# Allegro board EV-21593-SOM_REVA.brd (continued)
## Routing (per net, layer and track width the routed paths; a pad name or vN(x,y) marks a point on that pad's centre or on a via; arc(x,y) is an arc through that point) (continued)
DAI0_PIN10: length 48.7
  TOP w0.203: v1(33.82,45.34) U1.Y11
  L4_SIG w0.14: v1(58.04,19.43) 57.53,19.94 57.53,31.62 55.12,34.04 55.12,39.5 53.72,40.89 50.29,40.89 49.05,42.14 38.62,42.14 37.02,43.74 34.82,43.74 33.82,44.74 v1(33.82,45.34)
  BOTTOM w0.14: v1(58.04,19.43) 58.04,19.05 58.17,18.92 59.05,18.92 59.31,19.18 J1.21
DAI0_PIN11: length 51
  TOP w0.203: v1(34.62,45.34) U1.Y12
  L4_SIG w0.14: v1(34.62,45.34) 35.28,44.68 37.16,44.68 38.91,42.93 50.16,42.93 50.55,42.55 53.72,42.55 55.88,40.39 v1(58.55,40.39)
  L5_SIG w0.14: v1(58.55,40.39) 60.58,40.39 61.34,39.62 61.34,20.7 v1(61.85,20.19)
  BOTTOM w0.14: v1(61.85,20.19) 61.34,19.81 J1.23
DAI0_PIN12: length 51.6
  TOP w0.203: v1(34.62,46.14) U1.W12
  L4_SIG w0.14: v1(34.62,46.14) 35.01,45.75 35.59,45.75 35.81,45.52 35.81,45.19 36.07,44.93 37.29,44.93 38.48,43.74 49.91,43.74 50.72,42.93 54.23,42.93 55.88,41.27 58.8,41.27 59.31,40.77 59.31,39.5 58.8,38.99 57.91,38.99 57.4,38.48 57.4,32.89 59.31,30.99 59.31,21.72 58.93,21.34 v1(58.93,20.45)
  BOTTOM w0.14: v1(58.93,20.45) 59.31,20.45 J1.25
DAI0_PIN19: length 48.9
  TOP w0.203: v1(35.42,46.14) U1.W13
  L4_SIG w0.14: v1(59.05,42.93) 59.03,42.95 57.66,42.95 57.43,43.18 50.98,43.18 50.16,43.99 38.61,43.99 37.42,45.18 37.42,46.3 37.18,46.53 35.81,46.53 v1(35.42,46.14)
  L5_SIG w0.14: v1(61.85,25.15) 62.48,25.78 62.48,41.66 61.2,42.94 60.83,42.93 v1(59.05,42.93)
  BOTTOM w0.14: J1.39 61.34,24.89 v1(61.85,25.15)
DAI0_PIN20: length 48.9
  TOP w0.203: v1(34.62,46.94) U1.V12
  L4_SIG w0.14: v1(57.82,43.54) 52.96,43.54 52.85,43.43 51.11,43.43 50.29,44.25 39.16,44.25 38.22,45.18 38.22,47.1 37.98,47.33 35.01,47.33 v1(34.62,46.94)
  L5_SIG w0.14: v1(57.82,43.54) 56.64,43.54 56.26,43.16 56.26,38.1 57.53,36.83 57.53,27.05 v1(58.04,26.54)
  BOTTOM w0.14: v1(58.04,26.54) 58.04,25.78 58.29,25.53 J1.41
DAI1_PIN01: length 52.6
  TOP w0.203: v1(41.02,49.34) U1.R20
  L4_SIG w0.14: v1(41.02,49.34) 44.22,49.34 44.62,49.74 53.21,49.74 54.19,48.77 v1(54.23,48.77)
  L5_SIG w0.14: v1(54.23,48.77) 54.23,47.63 54.62,47.24 54.62,44.96 54.74,44.84 54.74,37.08 56.01,35.81 56.01,14.1 v1(55.12,13.21)
  BOTTOM w0.14: v1(55.12,13.21) 55.63,13.46 J1.4
DAI1_PIN02: length 56.3
  TOP w0.203: v1(39.42,50.14) U1.P18
  L4_SIG w0.14: v1(39.42,50.14) 39.82,50.54 44.29,50.54 45.09,51.34 49.66,51.34 50.32,50.67 53.85,50.67 v1(54.23,50.29)
  L5_SIG w0.14: v1(54.23,50.29) 54.74,49.78 54.74,48.2 55.63,47.31 55.63,45.47 55.12,44.96 55.12,37.34 56.39,36.07 56.39,14.99 56.9,14.48 v1(58.04,14.48)
  BOTTOM w0.14: v1(58.04,14.48) 57.66,14.1 J1.6
DAI1_PIN03: length 54.2
  TOP w0.203: v1(39.42,49.34) U1.R18
  L4_SIG w0.14: v1(39.42,49.34) 39.82,49.74 44.02,49.74 44.82,50.54 49.53,50.54 49.9,50.16 53.59,50.16 v1(54.23,49.53)
  L5_SIG w0.14: v1(55.12,14.48) 55.63,14.99 55.63,35.56 54.36,36.83 54.36,44.44 54.22,44.58 54.22,46.99 53.72,47.49 53.72,49.15 v1(54.23,49.53)
  BOTTOM w0.14: v1(55.12,14.48) 55.63,14.73 J1.8
DAI1_PIN04: length 52.2
  TOP w0.203: v1(41.02,48.54) U1.T20
  L4_SIG w0.14: v1(56.52,47.24) 56.49,47.27 54.25,47.27 52.58,48.94 45.02,48.94 44.22,48.14 42.86,48.14 42.46,48.54 v1(41.02,48.54)
  L5_SIG w0.14: v1(58.04,15.75) 57.28,15.75 56.77,16.26 56.77,36.32 55.5,37.59 55.5,44.7 56.52,45.72 v1(56.52,47.24)
  BOTTOM w0.14: v1(58.04,15.75) 57.66,15.37 J1.10
DAI1_PIN05: length 47.6
  TOP w0.203: v1(41.02,47.74) U1.U20
  L4_SIG w0.14: v1(41.02,47.74) 42.02,47.74 42.42,47.34 44.62,47.34 45.02,47.74 51.42,47.74 v1(52.22,46.94)
  L5_SIG w0.14: v1(55.12,15.75) 52.32,18.54 52.32,24.26 51.69,24.89 51.69,30.61 50.8,31.5 50.8,40.77 51.31,41.27 51.31,43.03 52.22,43.94 v1(52.22,46.94)
  BOTTOM w0.14: J1.12 55.63,16 v1(55.12,15.75)
DAI1_PIN06: length 50
  TOP w0.203: v1(40.22,48.54) U1.T19
  L4_SIG w0.14: v1(56.26,44.7) 56.26,46.1 55.75,46.61 54.36,46.61 54.23,46.74 54.23,46.74 52.83,48.14 44.82,48.14 44.42,47.74 42.62,47.74 42.22,48.14 40.62,48.14 v1(40.22,48.54)
  L5_SIG w0.14: v1(58.04,17.02) 57.4,17.02 57.15,17.27 57.15,36.58 55.88,37.85 55.88,44.32 v1(56.26,44.7)
  BOTTOM w0.14: v1(58.04,17.02) 57.66,16.64 J1.14
DAI1_PIN07: length 47.3
  TOP w0.203: v1(40.22,47.74) U1.U19
  L4_SIG w0.14: v1(53.82,45.74) 53.31,46.25 52.3,46.25 51.21,47.34 45.22,47.34 44.42,46.54 42.46,46.54 41.66,47.34 40.62,47.34 v1(40.22,47.74)
  L5_SIG w0.14: v1(53.82,45.74) 53.42,45.34 53.42,44.3 53.59,44.12 53.59,35.81 53.09,35.31 53.09,26.54 54.23,25.4 54.23,17.91 v1(55.12,17.02)
  BOTTOM w0.14: v1(55.12,17.02) 55.12,17.06 55.17,17.08 55.63,17.27 J1.16
DAI1_PIN08: length 54.4
  TOP w0.203: v1(40.22,49.34) U1.R19
  L4_SIG w0.14: v1(40.22,49.34) 40.62,48.94 44.42,48.94 44.82,49.34 52.84,49.34 54.46,47.72 57.3,47.72 v1(58.67,46.35)
  L5_SIG w0.14: v1(58.67,46.35) 58.67,45.16 59.25,44.58 59.25,44.07 58.62,43.43 58.62,41.91 57.63,40.92 57.63,39.52 58.17,38.99 59.18,38.99 60.45,37.72 60.45,19.69 59.56,18.8 58.55,18.8 v1(58.04,18.29)
  BOTTOM w0.14: J1.18 57.66,17.91 v1(58.04,18.29)
DAI1_PIN09: length 43.7
  TOP w0.203: v1(39.42,48.54) U1.T18
  L4_SIG w0.14: v1(55.12,18.67) 54.48,19.3 53.34,19.3 52.58,20.07 52.58,27.56 51.69,28.45 v1(45.97,28.45)
  L5_SIG w0.14: v1(45.97,28.45) 44.7,29.72 43.31,29.72 42.8,30.23 42.8,35.3 41.02,37.08 41.02,45.94 40.62,46.34 40.62,47.94 40.42,48.14 39.82,48.14 v1(39.42,48.54)
  BOTTOM w0.14: v1(55.12,18.67) 55.63,18.54 J1.20
DAI1_PIN10: length 43.3
  TOP w0.203: v1(39.42,47.74) U1.U18
  L4_SIG w0.14: v1(44.96,28.45) 45.72,29.21 51.56,29.21 52.96,27.81 52.96,20.57 53.59,19.94 54.61,19.94 v1(55.12,19.43)
  L5_SIG w0.14: v1(44.96,28.45) 44.07,29.34 43.18,29.34 42.16,30.35 42.16,31.09 40.62,32.64 40.62,45.54 40.42,45.74 40.02,45.74 39.82,45.94 39.82,47.34 v1(39.42,47.74)
  BOTTOM w0.14: v1(55.12,19.43) 55.63,19.18 J1.22
DAI1_PIN11: length 42.7
  TOP w0.203: v1(40.22,46.94) U1.V19
  L4_SIG w0.14: v1(40.22,46.94) 41.42,45.74 45.02,45.74 45.42,46.14 48.49,46.14 49.42,45.21 52.83,45.21 53.1,44.94 v1(53.82,44.94)
  L5_SIG w0.14: v1(53.82,44.94) 53.82,44.45 53.98,44.3 53.98,35.56 53.47,35.05 53.47,26.92 54.61,25.78 54.61,20.83 v1(55.12,20.32)
  BOTTOM w0.14: v1(55.12,20.32) 55.63,19.81 J1.24
DAI1_PIN12: length 47.8
  TOP w0.203: v1(41.02,46.94) U1.V20
  L4_SIG w0.14: v1(58.67,44.32) 58.17,44.32 57.91,44.07 55.75,44.07 54.48,45.35 53.34,45.35 53.09,45.59 50.61,45.59 49.66,46.54 45.02,46.54 44.62,46.14 41.82,46.14 v1(41.02,46.94)
  L5_SIG w0.14: v1(58.04,20.45) 58.04,24.64 59.82,26.42 59.82,35.43 57.15,38.1 57.15,42.55 57.53,42.93 58,42.93 58.22,43.15 58.22,43.87 v1(58.67,44.32)
  BOTTOM w0.14: v1(58.04,20.45) 57.66,20.45 J1.26
DAI1_PIN19: length 41.4
  TOP w0.203: v1(38.62,46.94) U1.V17
  L4_SIG w0.14: v1(52.62,43.94) 52.06,44.5 39.7,44.5 39.02,45.18 39.02,46.54 v1(38.62,46.94)
  L5_SIG w0.14: v1(52.62,43.94) 52.62,43.18 52.24,42.8 52.24,41.15 51.18,40.09 51.18,31.79 52.24,30.73 52.24,25.49 v1(53.59,24.13)
  BOTTOM w0.14: J1.40 54.99,24.89 54.23,24.13 v1(53.59,24.13)
DAI1_PIN20: length 38.1
  TOP w0.203: v1(39.42,46.14) U1.W18
  L4_SIG w0.14: v1(52.62,44.54) 52.3,44.86 41.61,44.86 40.72,45.75 39.81,45.75 v1(39.42,46.14)
  L5_SIG w0.14: v1(52.62,44.54) 53.21,43.95 53.21,41.4 52.45,40.64 52.45,31.37 52.7,31.12 52.7,26.03 v1(53.59,25.15)
  BOTTOM w0.14: J1.42 54.76,25.53 54.38,25.15 v1(53.59,25.15)
DMC0_A00: length 41
  TOP w0.203: U1.D19 v1(40.22,58.94) ; v1(36.22,74.34) U13.N3
  L5_SIG w0.14: v1(42.62,59.74) 44.22,61.34 44.22,64.61 44.07,64.76 44.07,70.14 44.27,70.34 45.14,70.34 45.34,70.54 45.34,75.74 44.94,76.14 36.82,76.14 36.62,75.94 U13.N3 v1(36.22,74.34)
  BOTTOM w0.14: v1(42.62,59.74) 42.22,59.34 40.62,59.34 v1(40.22,58.94) ; v1(36.22,74.34) 36.22,74.74 37.22,75.74 37.42,75.74 37.62,75.54 37.62,75.34 37.82,75.14 38.02,75.14 38.22,75.34 38.22,75.47 38.42,75.67 38.62,75.67 38.82,75.47 38.82,75.34 39.02,75.14 39.22,75.14 39.42,75.34 39.42,75.54 39.22,75.74 39.22,75.94 39.42,76.14 41.37,76.14 41.42,76.19 RN1.1
DMC0_A01: length 41.3
  TOP w0.203: v1(37.02,78.34) U13.P7 ; U1.D20 v1(41.02,58.94)
  L4_SIG w0.14: v1(37.02,78.34) 37.02,76.34 37.22,76.14 38.62,76.14 38.82,75.94 38.82,75.74 38.62,75.54 38.42,75.54 38.22,75.74 38.02,75.74 37.82,75.54 37.82,75.34 38.22,74.94 38.22,72.54 38.42,72.34 38.42,72.14 38.22,71.94 38.02,71.94 37.82,71.74 37.82,71.54 38.02,71.34 38.02,70.54 37.82,70.34 37.82,70.14 38.22,69.74 38.22,69.34 37.82,68.94 37.82,64.74 38.02,64.54 38.82,64.54 39.02,64.34 39.02,64.14 38.82,63.94 38.02,63.94 37.82,64.14 37.62,64.14 37.42,63.94 37.42,63.74 37.62,63.54 38.82,63.54 39.02,63.34 39.02,60.34 38.82,60.14 38.42,60.14 38.22,59.94 38.22,58.74 38.42,58.54 38.82,58.54 39.02,58.74 39.02,59.14 39.22,59.34 40.62,59.34 v1(41.02,58.94)
  BOTTOM w0.14: v1(37.02,78.34) 37.42,78.74 39.3,78.74 39.5,78.94 39.5,79.34 39.42,79.42 39.42,79.94 39.62,80.14 40.22,80.14 40.42,80.34 40.42,80.54 40.22,80.74 40.22,80.94 40.42,81.14 40.82,81.14 41.02,80.94 41.02,80.74 40.82,80.54 40.82,80.34 41.02,80.14 41.17,80.14 41.42,79.89 RN3.2
DMC0_A02: length 41.1
  TOP w0.14: v1(41.82,59.74) 41.42,59.34 U1.C20
  TOP w0.203: v1(37.02,74.34) U13.P3
  L5_SIG w0.14: v1(37.02,74.34) 37.02,75.54 37.22,75.74 44.43,75.74 44.83,75.34 44.83,71.14 44.63,70.94 43.42,70.94 43.22,70.74 43.22,66.34 43.02,66.14 42.67,66.14 42.55,66.01 42.55,65.66 42.67,65.53 43.56,65.53 43.69,65.4 43.69,64.39 43.82,64.26 43.82,61.94 43.62,61.74 43.42,61.74 43.22,61.94 43.02,61.94 42.82,61.74 42.42,61.74 42.06,62.1 41.75,62.1 41.62,61.98 41.62,60.34 41.82,60.14 v1(41.82,59.74)
  BOTTOM w0.14: v1(37.02,74.34) 37.42,73.94 39.14,73.94 39.42,73.66 39.42,71.94 39.62,71.74 41.22,71.74 41.42,71.94 41.42,73.29 41.62,73.49 RN2.2
DMC0_A03: length 41.3
  TOP w0.203: v1(36.22,73.54) U13.N2 ; U1.C19 v1(40.22,59.74)
  L5_SIG w0.14: v1(36.22,61.34) 36.22,61.94 35.62,62.54 35.22,62.54 35.02,62.74 35.02,64.94 35.22,65.14 36.42,65.14 36.62,65.34 36.62,65.94 37.02,66.34 37.02,66.54 37.22,66.74 37.42,66.74 37.62,66.54 37.82,66.54 38.02,66.74 38.02,66.94 37.82,67.14 37.22,67.14 37.02,67.34 37.02,67.54 37.22,67.74 37.42,67.74 37.62,67.54 37.82,67.54 38.02,67.74 38.02,67.94 37.82,68.14 37.22,68.14 37.02,68.34 37.02,68.54 37.22,68.74 37.42,68.74 37.62,68.54 37.82,68.54 38.02,68.74 38.02,68.94 37.82,69.14 37.22,69.14 37.02,69.34 37.02,70.34 37.22,70.54 37.42,70.54 37.62,70.34 37.82,70.34 38.02,70.54 38.02,70.74 37.82,70.94 37.22,70.94 37.02,71.14 37.02,71.34 37.22,71.54 37.42,71.54 37.62,71.34 37.82,71.34 38.02,71.54 38.02,71.74 37.82,71.94 36.02,71.94 35.82,72.14 35.82,73.14 v1(36.22,73.54)
  BOTTOM w0.14: v1(36.22,61.34) 35.82,60.94 35.82,59.54 36.02,59.34 U1.C19 v1(40.22,59.74) ; v1(36.22,73.54) 36.22,73.84 36.32,73.94 36.54,73.94 36.62,73.86 36.62,72.54 37.32,71.84 37.32,71.74 37.12,71.54 37.02,71.54 36.82,71.34 36.82,71.14 37.02,70.94 37.22,70.94 37.42,71.14 37.62,71.14 38.02,70.74 38.02,70.54 37.82,70.34 36.97,70.34 36.77,70.14 RN5.2
DMC0_A04: length 41.3
  TOP w0.203: U1.A19 v1(40.22,61.34) ; v1(37.02,79.14) U13.P8
  L4_SIG w0.14: v1(40.22,61.34) 40.22,62.34 39.82,62.74 39.82,63.74 39.42,64.14 39.42,64.74 39.22,64.94 38.42,64.94 38.22,65.14 38.22,66.54 38.42,66.74 38.62,66.74 38.82,66.54 38.82,65.94 39.02,65.74 39.22,65.74 39.42,65.94 39.42,66.94 39.22,67.14 38.42,67.14 38.22,67.34 38.22,67.54 38.42,67.74 38.82,67.74 39.02,67.54 39.22,67.54 39.42,67.74 39.42,67.94 39.22,68.14 38.42,68.14 38.22,68.34 38.22,68.54 38.42,68.74 38.82,68.74 39.02,68.54 39.22,68.54 39.42,68.74 39.42,68.94 39.22,69.14 38.82,69.14 38.62,69.34 38.62,69.74 38.82,69.94 39.22,69.94 39.42,70.14 39.42,70.34 39.22,70.54 39.02,70.54 38.82,70.34 38.62,70.34 38.42,70.54 38.42,70.74 38.62,70.94 39.22,70.94 39.42,71.14 39.42,71.34 39.22,71.54 39.02,71.54 38.82,71.74 38.82,72.34 39.02,72.54 39.02,74.94 39.22,75.14 39.22,76.34 39.02,76.54 37.62,76.54 37.42,76.74 U13.P8 v1(37.02,79.14)
  BOTTOM w0.14: v1(37.02,79.14) 37.42,79.54 37.42,80.34 37.82,80.74 37.82,82.14 38.02,82.34 39.17,82.34 39.37,82.54 39.37,84.34 39.17,84.54 37.77,84.54 RN4.1
DMC0_A05: length 41.2
  TOP w0.203: v1(37.02,73.54) U13.P2 ; U1.B20 v1(41.02,60.54)
  L5_SIG w0.14: v1(41.02,60.54) 40.62,60.94 39.22,60.94 39.02,61.14 39.02,61.54 38.82,61.74 37.22,61.74 37.02,61.94 37.02,62.34 36.62,62.74 36.62,63.34 36.82,63.54 36.82,63.74 36.62,63.94 36.62,64.14 36.82,64.34 37.02,64.34 37.42,63.94 37.62,63.94 37.82,64.14 37.82,65.14 38.02,65.34 38.22,65.34 38.42,65.14 38.42,64.94 38.22,64.74 38.22,64.14 38.42,63.94 39.22,63.94 39.42,64.14 39.42,64.34 39.22,64.54 39.02,64.54 38.82,64.74 38.82,64.94 39.02,65.14 39.02,65.54 39.22,65.74 39.82,65.74 40.02,65.94 40.02,66.14 39.82,66.34 39.42,66.34 39.22,66.14 39.02,66.14 38.82,66.34 38.82,66.54 39.02,66.74 39.82,66.74 40.02,66.94 40.02,67.14 39.82,67.34 39.42,67.34 39.22,67.14 39.02,67.14 38.82,67.34 38.82,67.54 39.02,67.74 39.82,67.74 40.02,67.94 40.02,72.54 39.82,72.74 39.82,72.94 40.02,73.14 40.02,73.34 39.82,73.54 39.62,73.54 39.22,73.14 37.42,73.14 v1(37.02,73.54)
  BOTTOM w0.14: RN5.3 37.27,69.79 37.42,69.94 38.22,69.94 38.42,69.74 38.82,69.74 39.02,69.94 39.42,69.94 39.62,70.14 39.62,70.34 39.42,70.54 38.82,70.54 37.82,71.54 37.82,71.94 37.42,72.34 37.42,73.14 v1(37.02,73.54)
DMC0_A06: length 41.3
  TOP w0.203: U1.B18 v1(39.42,60.54) ; v1(37.82,79.14) U13.R8
  L4_SIG w0.14: v1(37.82,79.14) U13.R8 38.22,77.54 38.42,77.34 41.42,77.34 41.62,77.14 41.62,74.14 41.42,73.94 40.22,73.94 40.02,73.74 40.02,73.54 40.22,73.34 40.42,73.34 40.62,73.54 41.42,73.54 41.62,73.34 41.62,73.14 41.42,72.94 40.22,72.94 40.02,72.74 40.02,72.54 40.22,72.34 40.42,72.34 40.62,72.54 41.22,72.54 41.42,72.34 41.42,72.14 41.22,71.94 40.42,71.94 40.22,71.74 40.22,71.54 40.42,71.34 40.62,71.34 40.82,71.54 41.02,71.54 41.22,71.34 41.22,71.14 41.02,70.94 40.42,70.94 40.22,70.74 40.22,62.94 40.62,62.54 40.62,61.14 40.42,60.94 39.82,60.94 v1(39.42,60.54)
  BOTTOM w0.14: RN3.4 41.82,80.89 41.82,81.14 42.02,81.34 42.22,81.34 42.42,81.54 42.42,81.74 42.22,81.94 38.42,81.94 38.22,81.74 38.22,79.54 v1(37.82,79.14)
DMC0_A07: length 41
  TOP w0.203: v1(37.82,73.54) U13.R2 ; U1.A18 v1(39.42,61.34)
  L5_SIG w0.14: v1(37.82,73.54) U13.R2 40.13,73.94 40.42,73.65 40.42,71.14 40.62,70.94 41.82,70.94 42.02,70.74 42.02,70.54 41.82,70.34 41.62,70.34 41.42,70.54 40.62,70.54 40.42,70.34 40.42,70.14 40.62,69.94 41.82,69.94 42.02,69.74 42.02,69.54 41.82,69.34 41.62,69.34 41.42,69.54 40.62,69.54 40.42,69.34 40.42,69.14 40.62,68.94 41.82,68.94 42.02,68.74 42.02,68.54 41.82,68.34 41.62,68.34 41.42,68.54 40.62,68.54 40.42,68.34 40.42,68.14 40.62,67.94 41.82,67.94 42.02,67.74 42.02,67.54 41.82,67.34 41.62,67.34 41.42,67.54 40.62,67.54 40.42,67.34 40.42,65.74 40.22,65.54 40.22,64.54 40.02,64.34 40.02,63.74 39.82,63.54 37.62,63.54 37.42,63.34 37.42,62.34 37.62,62.14 39.22,62.14 39.42,61.94 v1(39.42,61.34)
  BOTTOM w0.14: v1(37.82,73.54) 38.22,73.14 38.22,71.74 39.02,70.94 39.82,70.94 40.02,70.74 40.02,69.16 39.82,68.96 37.77,68.96 RN5.4
DMC0_A08: length 41.3
  TOP w0.203: v1(38.62,79.14) U13.T8 ; U1.A16 v1(37.82,61.34)
  L4_SIG w0.14: v1(41.02,59.74) 41.42,60.14 41.42,61.97 41.02,62.38 41.02,67.94 41.22,68.14 42.02,68.14 42.22,68.34 42.22,68.54 42.02,68.74 41.82,68.74 41.62,68.54 41.22,68.54 41.02,68.74 41.02,68.94 41.22,69.14 42.62,69.14 42.82,69.34 42.82,77.94 42.62,78.14 39.22,78.14 39.02,78.34 U13.T8 v1(38.62,79.14)
  BOTTOM w0.14: v1(37.82,61.34) 38.22,60.94 38.22,60.34 38.42,60.14 40.62,60.14 v1(41.02,59.74) ; v1(38.62,79.14) 39.02,79.54 39.02,80.34 39.22,80.54 39.62,80.54 39.82,80.74 39.82,80.94 39.62,81.14 39.22,81.14 38.98,80.9 38.76,80.9 38.62,81.04 38.62,81.34 38.82,81.54 41.22,81.54 41.42,81.34 41.42,80.59 41.62,80.39 RN3.3
DMC0_A09: length 41.3
  TOP w0.203: v1(37.82,74.34) U13.R3 ; U1.B16 v1(37.82,60.54)
  L5_SIG w0.14: v1(37.82,74.34) 37.82,75.06 37.95,75.18 38.23,75.18 38.35,75.06 38.35,74.99 38.61,74.74 44.13,74.74 44.32,74.55 44.32,74.27 44.2,74.14 43.22,74.14 43.02,74.34 42.62,74.34 42.42,74.14 42.42,73.94 42.62,73.74 44.08,73.74 44.21,73.61 44.21,73.28 44.07,73.14 43.42,73.14 43.22,73.34 43.02,73.34 42.82,73.14 42.82,66.74 42.62,66.54 41.42,66.54 41.22,66.34 41.22,66.14 41.42,65.94 41.42,64.54 40.82,63.94 40.82,62.34 40.62,62.14 v1(39.82,62.14)
  BOTTOM w0.14: v1(39.82,62.14) 39.42,61.74 37.62,61.74 37.42,61.54 37.42,60.94 v1(37.82,60.54) ; RN2.4 41.62,74.49 41.42,74.69 41.42,75.14 41.62,75.34 41.62,75.54 41.42,75.74 41.19,75.74 41,75.54 41,74.72 40.82,74.54 40.62,74.54 40.42,74.74 40.42,75.14 40.62,75.34 40.62,75.54 40.42,75.74 40.22,75.74 40.02,75.54 40.02,74.94 39.82,74.74 U13.R3 v1(37.82,74.34)
DMC0_A10: length 41.2
  TOP w0.203: v1(34.62,78.34) U13.L7 ; U1.A15 v1(37.02,61.34)
  L4_SIG w0.14: v1(37.02,61.34) 37.42,60.94 37.42,57.94 37.22,57.74 36.82,57.74 36.62,57.94 36.62,59.94 36.42,60.14 36.02,60.14 35.82,59.94 35.82,57.94 35.62,57.74 35.22,57.74 35.02,57.94 35.02,61.54 34.62,61.94 34.62,72.94 35.02,73.34 35.02,74.54 34.62,74.94 34.62,77.34 34.82,77.54 34.82,77.74 34.62,77.94 v1(34.62,78.34)
  BOTTOM w0.14: v1(34.62,78.34) 34.62,78.04 34.52,77.94 34.32,77.94 34.22,78.04 34.22,81.14 34.42,81.34 34.84,81.34 35.22,81.72 35.22,82.3 34.84,82.68 34.29,82.68 34.06,82.91 RN7.1
DMC0_A11: length 41.3
  TOP w0.203: U1.B15 v1(37.02,60.54) ; v1(37.82,78.34) U13.R7
  L4_SIG w0.14: v1(39.82,64.74) 39.82,71.54 39.62,71.74 39.62,74.34 39.82,74.54 40.62,74.54 40.82,74.34 41.02,74.34 41.22,74.54 41.22,74.74 41.02,74.94 39.82,74.94 39.62,75.14 39.62,75.34 39.82,75.54 40.62,75.54 40.82,75.34 41.02,75.34 41.22,75.54 41.22,75.74 41.02,75.94 39.82,75.94 39.62,76.14 39.62,76.34 39.82,76.54 40.62,76.54 40.82,76.34 41.02,76.34 41.22,76.54 41.22,76.74 41.02,76.94 38.02,76.94 37.82,77.14 v1(37.82,78.34)
  BOTTOM w0.14: v1(37.82,78.34) 37.42,77.94 36.17,77.94 35.97,77.74 35.97,77.54 36.17,77.34 36.82,77.34 37.05,77.57 41.41,77.57 41.53,77.69 RN1.4 ; v1(37.02,60.54) 36.62,60.94 36.62,61.94 36.82,62.14 39.02,62.14 39.82,62.94 v1(39.82,64.74)
DMC0_A12: length 41.3
  TOP w0.203: U1.B14 v1(36.22,60.54) ; v1(36.22,78.34) U13.N7
  L4_SIG w0.14: v1(36.22,78.34) 35.62,77.74 35.62,77.14 35.42,76.94 35.42,75.54 35.62,75.34 36.42,75.34 36.62,75.14 36.62,72.14 36.42,71.94 35.62,71.94 35.42,71.74 35.42,71.54 35.62,71.34 35.82,71.34 36.02,71.54 36.82,71.54 37.02,71.34 37.02,71.14 36.82,70.94 35.62,70.94 35.42,70.74 35.42,70.54 35.62,70.34 35.82,70.34 36.02,70.54 36.82,70.54 37.02,70.34 37.02,70.14 36.82,69.94 35.62,69.94 35.42,69.74 35.42,69.54 35.62,69.34 35.82,69.34 36.02,69.54 36.82,69.54 37.02,69.34 37.02,69.14 36.82,68.94 35.62,68.94 35.42,68.74 35.42,68.54 35.62,68.34 35.82,68.34 36.02,68.54 36.22,68.54 36.42,68.34 36.42,68.14 36.22,67.94 35.62,67.94 35.42,67.74 35.42,66.14 35.82,65.74 35.82,62.34 36.62,61.54 36.62,60.94 v1(36.22,60.54)
  BOTTOM w0.14: RN4.2 37.27,83.89 37.42,83.74 38.33,83.74 38.53,83.54 38.53,82.94 38.33,82.74 37.42,82.74 37.27,82.59 37.27,80.99 36.62,80.34 36.62,78.74 v1(36.22,78.34)
DMC0_A13: length 41.3
  TOP w0.14: U1.A14 35.82,62.1 36.2,62.48 37.59,62.48 37.82,62.71 v1(37.82,63.14)
  TOP w0.203: v1(38.62,74.34) U13.T3
  L5_SIG w0.14: v1(37.82,63.14) 38.42,62.54 38.82,62.54 39.42,63.14 39.62,63.14 40.02,62.74 40.22,62.74 40.42,62.94 40.42,64.14 41.02,64.74 41.02,65.74 40.82,65.94 40.82,66.74 41.02,66.94 42.22,66.94 42.42,67.14 42.42,71.14 42.22,71.34 41.02,71.34 40.82,71.54 40.82,71.74 41.02,71.94 41.22,71.94 41.42,71.74 42.22,71.74 42.42,71.94 42.42,72.34 42.22,72.54 41.62,72.54 41.42,72.34 41.02,72.34 40.82,72.54 40.82,72.74 41.02,72.94 42.22,72.94 42.42,73.14 42.42,73.34 42.22,73.54 42.02,73.54 41.82,73.34 41.02,73.34 40.82,73.54 40.82,73.74 41.02,73.94 41.22,73.94 41.42,73.74 41.62,73.74 41.82,73.94 41.82,74.14 41.62,74.34 v1(38.62,74.34)
  BOTTOM w0.14: RN2.3 41.22,73.99 41.02,73.79 41.02,73.54 40.82,73.34 40.48,73.34 40.28,73.14 40.28,72.94 40.48,72.74 40.82,72.74 41.02,72.54 41.02,72.34 40.82,72.14 40.02,72.14 39.82,72.34 39.82,73.54 40.22,73.94 40.22,74.14 40.02,74.34 v1(38.62,74.34)
DMC0_A14: length 41.3
  TOP w0.14: v1(40.62,65.34) 40.02,65.94 36.62,65.94 36.07,65.39 36.07,63.13 35.42,62.48 v1(35.42,61.34)
  TOP w0.203: U1.A13 v1(35.42,61.34) ; v1(38.62,78.34) U13.T7
  L4_SIG w0.14: v1(38.62,78.34) 38.62,77.94 38.82,77.74 42.22,77.74 42.42,77.54 42.42,74.74 42.22,74.54 42.22,72.74 42.42,72.54 42.42,71.94 42.22,71.74 41.82,71.74 41.62,71.54 41.62,71.34 41.82,71.14 42.22,71.14 42.42,70.94 42.42,70.74 42.22,70.54 40.82,70.54 40.62,70.34 40.62,70.14 40.82,69.94 41.02,69.94 41.22,70.14 41.91,70.14 42.04,70.01 42.04,69.67 41.91,69.54 40.82,69.54 40.62,69.34 v1(40.62,65.34)
  BOTTOM w0.14: v1(38.62,78.34) 39.82,78.34 40.02,78.54 40.02,79.54 40.22,79.74 40.42,79.74 40.62,79.54 40.62,79.34 40.42,79.14 40.42,78.94 40.62,78.74 40.62,78.54 40.42,78.34 40.42,78.18 40.62,77.98 40.82,77.98 40.98,78.14 41.42,78.14 41.62,78.34 41.62,78.54 41.42,78.74 41.2,78.74 41,78.94 41,79.19 41.2,79.39 RN3.1
DMC0_A15: length 41.3
  TOP w0.203: v1(35.42,78.34) U13.M7 ; U1.B13 v1(35.42,60.54)
  L4_SIG w0.14: v1(35.42,78.34) 35.82,78.74 35.82,81.34 35.42,81.74 34.62,81.74 34.42,81.54 34.42,81.34 34.62,81.14 35.22,81.14 35.42,80.94 35.42,80.74 35.22,80.54 35.02,80.54 34.82,80.74 34.22,80.74 34.02,80.94 33.82,80.94 33.62,80.74 33.62,80.54 33.82,80.34 34.62,80.34 35.02,79.94 35.02,78.14 35.22,77.94 35.22,77.34 35.02,77.14 35.02,75.14 35.22,74.94 35.62,74.94 35.82,74.74 35.82,72.54 35.62,72.34 35.22,72.34 35.02,72.14 35.02,62.34 35.82,61.54 35.82,60.94 v1(35.42,60.54)
  BOTTOM w0.14: RN4.4 36.27,84.54 36.02,84.54 35.88,84.68 35.56,84.68 35.48,84.6 35.48,84.28 35.82,83.94 35.82,82.34 35.62,82.14 35.62,81.34 35.22,80.94 34.82,80.94 34.62,80.74 34.62,78.94 34.82,78.74 35.02,78.74 v1(35.42,78.34)
DMC0_BA0: length 41.2
  TOP w0.203: v1(35.42,73.54) U13.M2 ; U1.B17 v1(38.62,60.54)
  L5_SIG w0.14: v1(38.62,60.54) 38.22,60.94 36.82,60.94 36.62,61.14 36.62,62.14 36.22,62.54 36.22,63.94 36.02,64.14 35.62,64.14 35.42,64.34 35.42,64.54 35.62,64.74 37.22,64.74 37.42,64.94 37.42,65.94 37.62,66.14 38.22,66.14 38.42,66.34 38.42,68.14 38.62,68.34 39.02,68.34 39.22,68.14 39.42,68.14 39.62,68.34 39.62,68.54 39.42,68.74 38.62,68.74 38.42,68.94 38.42,69.14 38.62,69.34 38.82,69.34 39.02,69.14 39.42,69.14 39.62,69.34 39.62,70.14 39.42,70.34 39.22,70.34 39.02,70.14 39.02,69.94 38.82,69.74 38.62,69.74 38.42,69.94 38.42,70.74 38.62,70.94 39.02,70.94 39.22,70.74 39.42,70.74 39.62,70.94 39.62,71.14 39.42,71.34 38.62,71.34 38.42,71.54 38.42,71.74 38.62,71.94 39.02,71.94 39.22,71.74 39.42,71.74 39.62,71.94 39.62,72.34 39.42,72.54 39.22,72.54 39.02,72.34 36.82,72.34 36.62,72.54 36.62,73.74 36.42,73.94 U13.M2 v1(35.42,73.54)
  BOTTOM w0.14: v1(35.42,73.54) 35.42,73.24 35.32,73.14 35.12,73.14 35.02,73.24 35.02,73.74 35.22,73.94 35.62,73.94 35.82,73.74 35.82,72.54 36.02,72.34 36.22,72.34 36.62,71.94 36.62,71.74 36.52,71.64 36.32,71.64 36.22,71.54 36.22,70.94 36.32,70.84 36.52,70.84 36.62,70.74 36.62,70.54 36.22,70.14 36.22,69.89 36.37,69.74 36.37,69.54 36.22,69.39 36.22,69.19 36.27,69.14 RN5.1
DMC0_BA1: length 41.3
  TOP w0.203: U1.A17 v1(38.62,61.34) ; v1(36.22,79.14) U13.N8
  L4_SIG w0.14: v1(36.22,79.14) U13.N8 36.62,77.14 36.42,76.94 36.02,76.94 35.82,76.74 35.82,75.94 36.02,75.74 37.22,75.74 37.42,75.54 37.42,67.74 37.22,67.54 36.02,67.54 35.82,67.34 35.82,67.14 36.02,66.94 36.42,66.94 36.62,67.14 37.22,67.14 37.42,66.94 37.42,66.74 37.22,66.54 36.42,66.54 36.22,66.34 36.22,66.14 36.42,65.94 37.22,65.94 37.42,65.74 37.42,65.34 37.22,65.14 36.42,65.14 36.22,64.94 36.22,64.74 36.42,64.54 36.62,64.54 36.82,64.74 37.02,64.74 37.22,64.54 37.22,64.34 37.02,64.14 36.42,64.14 36.22,63.94 36.22,63.14 36.62,62.74 37.42,62.74 37.62,62.54 37.62,61.94 37.82,61.74 38.02,61.74 38.22,61.94 38.22,62.14 38.02,62.34 38.02,62.54 38.22,62.74 38.42,62.74 38.62,62.54 v1(38.62,61.34)
  BOTTOM w0.14: v1(36.22,79.14) 35.82,79.54 35.22,79.54 35.02,79.74 35.02,80.34 35.22,80.54 35.62,80.54 35.82,80.74 35.82,80.94 36.02,81.14 36.5,81.14 36.7,81.34 36.7,81.54 36.5,81.74 36.34,81.74 36.22,81.86 36.22,82.04 36.32,82.14 36.65,82.14 36.78,82.27 36.78,82.38 36.62,82.54 36.62,82.74 36.82,82.94 37.02,82.94 37.22,83.14 37.22,83.34 36.77,83.79 RN4.3
DMC0_BA2: length 41.3
  TOP w0.14: v1(41.82,58.94) 41.02,58.14 40.22,58.14 U1.E19
  TOP w0.203: v1(35.42,74.34) U13.M3
  L5_SIG w0.14: v1(41.82,58.94) 41.42,59.34 41.42,59.94 41.22,60.14 36.02,60.14 35.82,60.34 35.82,61.74 35.42,62.14 34.82,62.14 34.62,62.34 34.62,65.14 35.02,65.54 35.02,65.74 34.62,66.14 34.62,66.34 34.82,66.54 35.02,66.54 35.22,66.34 35.62,66.34 35.82,66.54 36.02,66.54 36.22,66.34 36.42,66.34 36.62,66.54 36.62,66.74 36.42,66.94 34.82,66.94 34.62,67.14 34.62,67.34 34.82,67.54 35.22,67.54 35.42,67.34 36.33,67.34 36.62,67.63 36.62,71.34 36.42,71.54 35.22,71.54 35.02,71.74 35.02,73.94 v1(35.42,74.34)
  BOTTOM w0.14: RN1.2 41.03,76.69 40.98,76.74 39.72,76.74 39.59,76.61 39.15,76.61 39.02,76.74 38.82,76.74 38.62,76.54 38.62,76.34 38.42,76.14 38.22,76.14 38.02,76.34 38.02,76.54 37.82,76.74 37.62,76.74 35.82,74.94 U13.M3 v1(35.42,74.34)
DMC0_CK: length 33.6
  TOP w0.203: U1.J20 v1(41.02,54.94) ; v1(33.02,78.34) U13.J7
  L4_SIG w0.076: v1(33.02,78.34) 33.02,77.89 32.89,77.76 32.89,74.97 32.62,74.7 32.62,73.19 32.89,72.92 32.89,68.91 32.52,68.54 32.52,67.01 32.89,66.64 32.89,57.27 34.32,55.84 34.75,55.84 35.05,55.54 35.05,54.86 35.31,54.61 35.88,54.61 35.95,54.54 U1.J20 v1(41.02,54.94)
  BOTTOM w0.14: R16.1 33.02,77.42 v1(33.02,78.34)
DMC0_CKE: length 41.3
  TOP w0.203: v1(33.82,79.94) U13.K9 ; U1.H20 v1(41.02,55.74)
  L4_SIG w0.14: v1(41.02,55.74) 41.02,56.04 40.92,56.14 38.42,56.14 38.22,56.34 38.22,56.74 38.02,56.94 34.42,56.94 34.22,57.14 34.22,78.74 34.62,79.14 34.62,79.74 34.42,79.94 v1(33.82,79.94)
  BOTTOM w0.14: v1(33.82,79.94) 33.82,81.54 34.02,81.74 34.62,81.74 34.82,81.94 34.82,82.14 34.62,82.34 34.22,82.34 34.02,82.14 32.89,82.14 32.77,82.27 32.77,82.42 32.89,82.55 33.15,82.55 33.27,82.68 33.27,82.9 33.15,83.02 32.89,83.02 32.77,83.15 32.77,83.44 32.89,83.57 33.44,83.57 33.56,83.69 RN7.2
DMC0_DQ00: length 33.4
  TOP w0.203: v1(25.82,54.94) U1.J2 ; U13.E3 v1(29.82,74.34)
  L5_SIG w0.14: v1(25.82,54.94) 26.22,55.34 26.22,55.94 26.42,56.14 26.82,56.14 27.02,55.94 27.02,55.54 27.22,55.34 27.62,55.34 27.82,55.54 27.82,55.94 28.02,56.14 28.42,56.14 28.62,56.34 28.62,67.14 28.42,67.34 27.62,67.34 27.42,67.54 27.42,67.74 27.62,67.94 28.42,67.94 28.62,68.14 28.62,68.34 28.42,68.54 27.22,68.54 27.02,68.74 27.02,68.94 27.22,69.14 28.42,69.14 28.62,69.34 28.62,69.94 28.22,70.34 28.22,70.54 28.62,70.94 28.62,72.94 28.42,73.14 27.22,73.14 27.02,73.34 27.02,73.74 27.22,73.94 28.42,73.94 28.62,74.14 28.62,74.54 28.82,74.74 29.42,74.74 v1(29.82,74.34)
DMC0_DQ01: length 33.4
  TOP w0.203: v1(25.02,58.14) U1.E1 ; U13.F7 v1(30.62,78.34)
  L5_SIG w0.14: v1(25.02,58.14) 25.42,58.54 25.42,66.14 24.82,66.74 24.82,76.34 25.02,76.54 33.62,76.54 33.82,76.74 33.82,77.74 33.62,77.94 U13.F7 v1(30.62,78.34)
DMC0_DQ02: length 33.4
  TOP w0.203: v1(25.02,55.74) U1.H1 ; U13.F2 v1(30.62,73.54)
  L5_SIG w0.14: v1(25.02,55.74) U1.H1 25.42,54.74 25.62,54.54 29.22,54.54 29.42,54.74 29.42,61.74 29.02,62.14 29.02,68.14 29.22,68.34 29.22,68.54 29.02,68.74 29.02,68.94 29.22,69.14 29.62,69.14 29.82,69.34 29.82,69.54 29.62,69.74 29.22,69.74 29.02,69.94 29.02,70.14 29.22,70.34 30.42,70.34 30.62,70.54 30.62,70.74 30.42,70.94 29.22,70.94 29.02,71.14 29.02,71.34 29.22,71.54 30.42,71.54 30.62,71.74 30.62,71.94 30.42,72.14 29.62,72.14 29.42,72.34 29.42,73.74 29.62,73.94 30.22,73.94 v1(30.62,73.54)
DMC0_DQ03: length 33.5
  TOP w0.203: U13.F8 v1(30.62,79.14) ; v1(25.02,58.94) U1.D1
  L5_SIG w0.14: v1(30.62,79.14) 30.22,78.74 29.62,78.74 29.42,78.54 29.42,78.14 29.22,77.94 28.82,77.94 28.62,78.14 28.62,78.54 28.42,78.74 28.02,78.74 27.82,78.54 27.82,78.14 27.62,77.94 27.22,77.94 27.02,78.14 27.02,78.54 26.82,78.74 26.42,78.74 26.22,78.94 26.02,78.94 25.82,78.74 25.82,78.54 26.02,78.34 26.02,78.14 25.82,77.94 25.02,77.94 24.02,76.94 24.02,66.14 24.62,65.54 24.62,62.34 24.02,61.74 24.02,60.14 24.42,59.74 24.42,59.54 24.02,59.14 24.02,58.14 24.22,57.94 24.42,57.94 24.62,58.14 24.62,58.34 24.42,58.54 24.42,58.74 24.62,58.94 v1(25.02,58.94)
DMC0_DQ04: length 33.4
  TOP w0.203: v1(25.82,56.54) U1.G2 ; U13.H3 v1(32.22,74.34)
  L5_SIG w0.14: v1(32.22,74.34) 31.82,73.94 31.82,67.54 31.02,66.74 31.02,56.14 30.62,55.74 30.62,53.54 30.42,53.34 24.42,53.34 24.22,53.54 24.22,55.94 24.42,56.14 25.42,56.14 v1(25.82,56.54)
DMC0_DQ05: length 33.4
  TOP w0.203: v1(25.82,58.14) U1.E2 ; U13.H8 v1(32.22,79.14)
  L5_SIG w0.14: v1(32.22,79.14) U13.H8 34.02,78.74 34.22,78.54 34.22,77.54 34.42,77.34 34.42,76.34 34.22,76.14 25.42,76.14 25.22,75.94 25.22,67.14 26.22,66.14 26.22,58.54 v1(25.82,58.14)
DMC0_DQ06: length 33.4
  TOP w0.203: v1(25.02,54.94) U1.J1 ; U13.G2 v1(31.42,73.54)
  L5_SIG w0.14: v1(31.42,73.54) 31.02,73.14 31.02,69.14 30.62,68.74 29.82,68.74 29.62,68.54 29.62,68.34 29.82,68.14 30.82,68.14 31.02,67.94 31.02,67.74 30.82,67.54 29.62,67.54 29.42,67.34 29.42,67.14 29.62,66.94 30.22,66.94 30.42,66.74 30.42,66.54 30.22,66.34 29.82,66.34 29.42,65.94 29.42,62.54 29.62,62.34 30.02,62.34 30.22,62.14 30.22,53.94 30.02,53.74 24.82,53.74 24.62,53.94 24.62,54.54 v1(25.02,54.94)
DMC0_DQ07: length 33.4
  TOP w0.203: v1(25.02,56.54) U1.G1 ; U13.H7 v1(32.22,78.34)
  L5_SIG w0.14: v1(32.22,78.34) 31.82,78.74 31.82,79.34 31.62,79.54 25.82,79.54 23.62,77.34 23.62,65.94 24.22,65.34 24.22,62.54 23.62,61.94 23.62,57.94 v1(25.02,56.54)
DMC0_DQ08: length 33.5
  TOP w0.203: U13.D7 v1(29.02,78.34) ; v1(25.82,59.74) U1.C2
  BOTTOM w0.14: v1(25.82,59.74) 26.22,60.14 26.22,66.94 25.82,67.34 23.42,67.34 23.22,67.54 23.22,68.34 23.02,68.54 21.82,68.54 21.62,68.74 21.62,68.94 21.82,69.14 22.62,69.14 22.82,69.34 22.82,69.54 22.62,69.74 21.82,69.74 21.62,69.94 21.62,77.74 21.82,77.94 26.82,77.94 27.02,78.14 27.02,78.54 27.22,78.74 28.62,78.74 v1(29.02,78.34)
DMC0_DQ09: length 33.4
  TOP w0.203: v1(29.02,60.54) U1.B6 ; U13.C3 v1(28.22,74.34)
  BOTTOM w0.14: v1(28.22,74.34) 28.22,74.74 28.42,74.94 28.62,74.94 28.82,75.14 28.82,76.34 29.02,76.54 29.22,76.54 29.42,76.34 29.42,75.14 29.62,74.94 29.82,74.94 30.02,75.14 30.02,76.14 30.22,76.34 30.42,76.34 30.62,76.14 30.62,75.14 30.82,74.94 31.02,74.94 31.22,75.14 31.22,75.94 31.42,76.14 31.62,76.14 31.82,75.94 31.82,66.54 31.22,65.94 31.22,62.34 31.02,62.14 31.02,58.74 30.82,58.54 28.82,58.54 28.62,58.74 28.62,60.14 v1(29.02,60.54)
DMC0_DQ10: length 33.4
  TOP w0.203: U13.C8 v1(28.22,79.14) ; v1(28.22,60.54) U1.B5
  BOTTOM w0.14: v1(28.22,79.14) 28.62,79.54 29.22,79.54 29.42,79.34 29.42,78.14 30.82,76.74 32.02,76.74 32.62,76.14 32.62,69.14 32.22,68.74 32.22,66.34 31.62,65.74 31.62,62.94 31.82,62.74 31.82,57.94 31.62,57.74 28.02,57.74 27.82,57.94 27.82,60.14 v1(28.22,60.54)
DMC0_DQ11: length 33.4
  TOP w0.203: v1(28.22,61.34) U1.A5 ; U13.C2 v1(28.22,73.54)
  BOTTOM w0.14: v1(28.22,73.54) 28.62,73.14 28.62,72.54 28.82,72.34 29.22,72.34 29.42,72.54 29.42,72.94 29.62,73.14 30.02,73.14 30.22,72.94 30.22,71.94 30.02,71.74 28.42,71.74 28.22,71.54 28.22,71.34 28.42,71.14 29.62,71.14 29.82,70.94 29.82,70.74 29.62,70.54 28.42,70.54 28.22,70.34 28.22,70.14 28.42,69.94 29.62,69.94 29.82,69.74 29.82,69.54 29.62,69.34 28.82,69.34 28.62,69.14 28.62,68.94 28.82,68.74 29.62,68.74 29.82,68.54 29.82,68.34 29.62,68.14 28.82,68.14 28.62,67.94 28.62,67.74 28.82,67.54 29.62,67.54 29.82,67.34 29.82,67.14 29.62,66.94 28.82,66.94 28.62,66.74 28.62,66.54 28.82,66.34 29.42,66.34 29.62,66.14 29.62,65.94 29.42,65.74 28.82,65.74 28.62,65.54 28.62,65.34 28.82,65.14 29.42,65.14 29.62,64.94 29.62,64.74 29.42,64.54 28.82,64.54 28.62,64.34 28.62,64.14 28.82,63.94 29.42,63.94 29.62,63.74 29.62,63.54 29.42,63.34 28.82,63.34 28.62,63.14 28.62,62.94 28.82,62.74 29.42,62.74 29.62,62.54 29.62,62.34 29.42,62.14 28.42,62.14 28.22,61.94 v1(28.22,61.34)
DMC0_DQ12: length 33.4
  TOP w0.203: U13.A7 v1(26.62,78.34) ; v1(25.82,61.34) U1.A2
  BOTTOM w0.14: v1(25.82,61.34) 25.82,66.34 25.22,66.94 21.42,66.94 21.22,67.14 21.22,67.34 21.42,67.54 22.62,67.54 22.82,67.74 22.82,67.94 22.62,68.14 21.42,68.14 21.22,68.34 21.22,78.74 21.42,78.94 21.62,78.94 21.82,78.74 21.82,78.54 22.02,78.34 22.22,78.34 22.42,78.54 22.42,78.74 22.62,78.94 22.82,78.94 23.02,78.74 23.02,78.54 23.22,78.34 23.42,78.34 23.62,78.54 23.62,78.74 23.82,78.94 24.02,78.94 24.22,78.74 24.22,78.54 24.42,78.34 24.62,78.34 24.82,78.54 24.82,78.74 25.02,78.94 25.22,78.94 25.42,78.74 25.42,78.54 25.62,78.34 v1(26.62,78.34)
DMC0_DQ13: length 33.4
  TOP w0.203: U13.A2 v1(26.62,73.54) ; v1(26.62,60.54) U1.B3
  BOTTOM w0.14: v1(26.62,60.54) 27.02,60.94 27.02,68.34 26.62,68.74 26.62,69.14 26.42,69.34 24.22,69.34 24.02,69.54 24.02,69.74 24.22,69.94 26.42,69.94 26.62,70.14 26.62,70.34 26.42,70.54 24.22,70.54 24.02,70.74 24.02,70.94 24.22,71.14 26.42,71.14 26.62,71.34 26.62,71.54 26.42,71.74 24.22,71.74 24.02,71.94 24.02,72.14 24.22,72.34 26.02,72.34 26.22,72.54 26.22,72.74 26.02,72.94 24.22,72.94 24.02,73.14 24.02,73.74 24.22,73.94 24.42,73.94 24.82,73.54 25.02,73.54 25.22,73.74 25.62,73.74 25.82,73.54 v1(26.62,73.54)
DMC0_DQ14: length 33.5
  TOP w0.203: v1(26.62,58.94) U1.D3 ; U13.B8 v1(27.42,79.14)
  BOTTOM w0.14: v1(26.62,58.94) 26.22,59.34 25.62,59.34 25.42,59.54 25.42,66.14 25.02,66.54 21.02,66.54 20.82,66.74 20.82,79.34 21.02,79.54 27.02,79.54 v1(27.42,79.14)
DMC0_DQ15: length 33.4
  TOP w0.203: U13.A3 v1(26.62,74.34) ; v1(26.62,61.34) U1.A3
  BOTTOM w0.14: v1(26.62,74.34) 22.22,74.34 22.02,74.14 22.02,73.94 22.42,73.54 22.42,73.34 22.02,72.94 22.02,72.74 22.22,72.54 22.62,72.54 22.82,72.74 23.42,72.74 23.62,72.54 23.62,72.14 23.42,71.94 22.22,71.94 22.02,71.74 22.02,71.54 22.22,71.34 23.42,71.34 23.62,71.14 23.62,70.94 23.42,70.74 22.22,70.74 22.02,70.54 22.02,70.34 22.22,70.14 23.42,70.14 23.62,69.94 23.62,69.14 23.82,68.94 26.02,68.94 26.22,68.74 26.22,68.54 26.02,68.34 23.82,68.34 23.62,68.14 23.62,67.94 23.82,67.74 26.22,67.74 26.62,67.34 v1(26.62,61.34)
DMC0_LDM: length 33.4
  TOP w0.203: v1(25.02,59.74) U1.C1 ; U13.E7 v1(29.82,78.34)
  L5_SIG w0.14: v1(29.82,78.34) 29.82,77.74 30.02,77.54 30.22,77.54 30.42,77.74 30.62,77.74 30.82,77.54 32.02,77.54 32.22,77.34 32.22,77.14 32.02,76.94 29.42,76.94 29.22,77.14 29.22,77.34 29.02,77.54 28.82,77.54 28.62,77.34 28.62,77.14 28.42,76.94 28.22,76.94 28.02,77.14 28.02,77.34 27.82,77.54 27.62,77.54 27.42,77.34 27.42,77.14 27.22,76.94 27.02,76.94 26.82,77.14 26.82,77.74 26.62,77.94 26.42,77.94 26.22,77.74 26.22,77.14 26.02,76.94 24.62,76.94 24.42,76.74 24.42,66.34 25.02,65.74 25.02,62.14 24.42,61.54 24.42,60.34 v1(25.02,59.74)
DMC0_LDQS: length 33.2
  TOP w0.203: U13.F3 v1(30.62,74.34) ; v1(25.82,57.34) U1.F2
  L5_SIG w0.076: v1(25.82,57.34) U1.F2 27.62,56.94 27.82,57.14 27.82,61.72 27.56,61.98 27.56,66.42 26.16,67.82 26.16,69.6 26.29,69.72 27.3,69.72 27.56,69.98 27.56,70.48 27.3,70.74 26.29,70.74 26.16,70.87 26.16,71.12 26.29,71.25 27.56,71.25 27.81,71.5 27.81,72.01 27.56,72.26 26.29,72.26 26.16,72.39 26.16,75.18 26.29,75.31 27.05,75.31 27.18,75.18 28.07,75.18 28.19,75.31 30.73,75.31 30.86,75.18 30.86,74.55 v1(30.62,74.34)
DMC0_ODT: length 41.3
  TOP w0.203: v1(33.82,72.74) U13.K1 ; U1.H19 v1(40.22,55.74)
  L5_SIG w0.14: v1(33.82,72.74) 33.42,72.34 33.42,66.74 33.02,66.34 33.02,58.54 33.22,58.34 33.42,58.34 33.62,58.54 34.82,58.54 35.02,58.34 35.02,57.94 35.22,57.74 35.62,57.74 35.82,57.94 35.82,58.34 36.02,58.54 36.42,58.54 36.62,58.34 36.62,57.94 36.82,57.74 37.22,57.74 37.42,57.94 37.42,58.34 37.62,58.54 39.62,58.54 40.62,57.54 40.62,57.14 40.42,56.94 40.02,56.94 39.82,56.74 39.82,55.54 40.02,55.34 41.42,55.34 41.62,55.54 41.62,55.94 41.42,56.14 40.62,56.14 v1(40.22,55.74)
  BOTTOM w0.14: RN6.2 33.57,69.44 33.42,69.59 33.42,69.94 33.62,70.14 33.82,70.14 34.02,69.94 34.42,69.94 34.62,70.14 34.62,70.34 34.42,70.54 33.62,70.54 33.42,70.74 33.42,70.94 33.62,71.14 33.82,71.14 34.02,70.94 34.42,70.94 34.62,71.14 34.62,71.34 34.42,71.54 33.82,71.54 33.42,71.94 33.42,72.34 v1(33.82,72.74)
DMC0_RZQ: length 4.7
  TOP w0.203: v1(40.22,56.54) U1.G19
  BOTTOM w0.14: R1.1 42.82,54.94 41.62,56.14 40.62,56.14 v1(40.22,56.54)
DMC0_UDM: length 33.4
  TOP w0.203: v1(29.02,61.34) U1.A6 ; U13.D3 v1(29.02,74.34)
  BOTTOM w0.14: v1(29.02,74.34) 29.42,73.94 30.82,73.94 31.02,73.74 31.02,72.54 30.62,72.14 30.62,71.94 30.82,71.74 30.92,71.74 31.12,71.94 31.22,71.94 31.42,71.74 31.42,71.14 31.22,70.94 30.82,70.94 30.62,71.14 30.42,71.14 30.22,70.94 30.22,70.74 30.42,70.54 31.22,70.54 31.42,70.34 31.42,70.14 31.22,69.94 30.42,69.94 30.22,69.74 30.22,69.34 30.42,69.14 31.22,69.14 31.42,68.94 31.42,68.74 31.22,68.54 30.42,68.54 30.22,68.34 30.22,68.14 30.42,67.94 31.22,67.94 31.42,67.74 31.42,67.54 31.22,67.34 30.42,67.34 30.22,67.14 30.22,66.94 30.42,66.74 30.82,66.74 31.02,66.54 31.02,66.34 30.82,66.14 30.22,66.14 30.02,65.94 30.02,65.74 30.22,65.54 30.62,65.54 30.82,65.34 30.82,65.14 30.62,64.94 30.22,64.94 30.02,64.74 30.02,64.54 30.22,64.34 30.62,64.34 30.82,64.14 30.82,63.94 30.62,63.74 30.22,63.74 30.02,63.54 30.02,63.34 30.22,63.14 30.62,63.14 30.82,62.94 30.82,62.74 30.62,62.54 30.22,62.54 30.02,62.34 30.02,61.94 30.22,61.74 30.22,59.54 30.02,59.34 29.62,59.34 29.42,59.54 U1.A6 v1(29.02,61.34)
DMC0_UDQS: length 33.4
  TOP w0.203: v1(27.42,60.54) U1.B4 ; U13.C7 v1(28.22,78.34)
  BOTTOM w0.089: v1(28.22,78.34) 28.55,77.93 28.55,77.37 27.57,76.39 25.34,76.39 24.64,77.09 22.54,77.09 22.4,76.95 22.4,75.55 22.54,75.41 22.96,75.41 23.1,75.55 23.1,76.25 23.38,76.53 23.94,76.53 24.22,76.25 24.22,75.55 24.36,75.41 25.9,75.41 26.31,75.83 27.29,75.83 27.57,75.55 27.57,75.1 27.82,74.85 27.82,72.34 27.57,72.09 27.57,69.27 27.99,68.85 27.99,62.42 27.82,62.25 27.82,60.94 v1(27.42,60.54)
DMC0_VREF: length 48.1
  TOP w0.305: R7.2 44.7,80.94 44.7,80.14 44.94,77.98 44.96,77.85 44.83,77.98 ; R8.2 46.98,75.78 45.09,77.72 45.06,75.78 45.06,75.31 45.05,75.19 44.95,66.79 44.95,66.68 44.83,66.79
  TOP w0.406: v2(44.83,65.53) 44.83,74.3 45.05,75.19 45.09,75.31 45.06,75.78 44.96,77.85
  L4_SIG w0.305: v2(44.83,65.53) 44.58,65.53 44.58,56.54 v1(45.42,56.54)
  BOTTOM w0.406: R2.1 v1(45.42,56.54) C10.1 47.02,56.54
HADC0_VIN0: length 48
  TOP w0.203: v1(40.22,50.94) U1.N19
  L4_SIG w0.14: v1(40.22,50.94) 40.62,51.34 44.07,51.34 45.43,52.7 55.24,52.7 60.58,47.37 60.58,28.45 60.83,28.19 62.23,28.19 62.48,27.94 62.48,27.3 62.23,27.05 v1(61.85,27.05)
  BOTTOM w0.14: v1(61.85,27.05) 61.47,27.43 J1.47
HADC0_VIN1: length 45.1
  TOP w0.203: v1(41.02,50.94) U1.N20
  L4_SIG w0.14: v1(41.02,50.94) 44.2,50.94 45.58,52.32 54.99,52.32 60.2,47.12 60.2,27.94 60.45,27.69 v1(61.85,27.69)
  BOTTOM w0.14: J1.49 61.47,28.07 v1(61.85,27.69)
HADC0_VIN2: length 46.8
  TOP w0.203: v1(40.22,51.74) U1.M19
  L4_SIG w0.14: v1(40.22,51.74) 40.62,52.14 43.81,52.14 45.14,53.47 55.75,53.47 61.34,47.88 61.34,30.1 61.59,29.84 62.23,29.84 62.48,29.59 62.48,28.96 62.23,28.7 v1(61.85,28.7)
  BOTTOM w0.14: J1.51 61.85,28.7 v1(61.85,28.7)
HADC0_VIN3: length 43.9
  TOP w0.203: v1(41.02,51.74) U1.M20
  L4_SIG w0.14: v1(61.85,29.34) 61.21,29.34 60.96,29.59 60.96,47.62 55.5,53.09 45.29,53.09 43.94,51.74 v1(41.02,51.74)
  BOTTOM w0.14: J1.53 61.85,29.34 v1(61.85,29.34)
ID0: length 18.1
  TOP w0.14: v2(52.45,10.54) R126.2 53.21,10.51 53.21,9.84 52.58,9.2 U22.1
  L4_SIG w0.14: v2(52.45,10.54) 50.04,10.54 48.39,8.89 40.13,8.89 v1(39.5,8.26)
  BOTTOM w0.14: J2.76 39.42,7.66 39.5,7.74 v1(39.5,8.26)
ID1: length 16.8
  TOP w0.14: U22.3 52.45,7.28 v2(52.45,5.97) R125.2
  L4_SIG w0.14: v2(52.45,5.97) 49.91,5.97 47.62,8.26 v1(40.51,8.26)
  BOTTOM w0.14: v1(40.51,8.26) 40.05,7.79 J2.78
INTVCC: length 16.5
  TOP w0.254: R56.1 20.7,14.1 19.81,14.99 U15.3
  TOP w0.305: R56.1 22.86,13.82 22.73,13.69 C167.2 22.73,13.33 v2(24.13,13.33) ; R58.1 v2(15.24,12.19)
  L4_SIG w0.305: v2(24.13,13.33) 23.62,12.83 18.8,12.83 18.41,13.21 16.26,13.21 v2(15.24,12.19)
JTG0_TCK/SWCLK: length 94.9
  TOP w0.14: v1(33.82,62.34) 33.02,63.14 33.02,66.93 31.88,68.07 26.03,68.07 25.15,68.96 25.15,71.63 24.64,72.14 v2(9.02,72.14) ; v1(5.46,28.7) 4.06,30.1 4.06,46.35 2.79,47.62 2.79,54.74 3.18,55.12 5.71,55.12 5.97,54.86 5.97,53.59 P1.4
  TOP w0.203: U1.B11 v1(33.82,59.74)
  L4_SIG w0.14: v2(8.89,52.96) 5.97,52.96 P1.4
  L5_SIG w0.14: v2(9.02,72.14) 9.02,71.5 7.49,69.98 7.49,60.58 9.4,58.67 9.4,53.47 v2(8.89,52.96)
  BOTTOM w0.14: v1(5.46,28.7) J3.50 ; v1(33.82,59.74) v1(33.82,62.34)
JTG0_TDI: length 116.3
  TOP w0.14: v1(8.51,27.18) 8.26,27.43 4.06,27.43 2.54,28.96 2.54,45.47 1.27,46.74 1.27,56.13 2.29,57.15 5.71,57.15 6.99,55.88 6.99,53.85 7.62,53.21 7.62,50.8 6.99,50.16 P1.8
  TOP w0.203: v1(35.42,59.74) U1.C13
  BOTTOM w0.14: v1(35.42,59.74) U1.C13 35.02,58.74 35.22,58.54 35.62,58.54 35.82,58.34 35.82,57.14 36.02,56.94 36.42,56.94 36.62,56.74 36.62,52.34 36.42,52.14 32.82,52.14 32.62,51.94 32.62,47.54 32.42,47.34 28.02,47.34 27.82,47.14 27.82,44.32 27.57,44.07 25.4,44.07 25.15,43.81 25.15,37.34 24.77,36.96 20.95,36.96 20.57,36.58 20.57,25.15 19.94,24.51 10.16,24.51 9.27,25.4 9.27,26.42 v1(8.51,27.18) 8,27.43 J3.54
JTG0_TDO/SWO: length 102.1
  TOP w0.14: 5.08,51.43 6.73,51.43 7.11,51.82 7.11,52.96 6.48,53.59 6.48,55.63 5.46,56.64 2.67,56.64 1.78,55.75 1.78,47.12 3.05,45.85 3.05,29.34 4.57,27.81 8.26,27.81 v1(8.51,28.07)
  TOP w0.203: v1(33.82,58.94) U1.C11
  BOTTOM w0.14: J3.52 8.51,28.07 v1(8.51,28.07) 9.4,28.96 18.54,28.96 19.18,29.59 19.18,38.73 20.95,40.51 24.51,40.51 24.77,40.77 24.77,44.2 25.02,44.45 26.77,44.45 27.02,44.7 27.02,47.94 27.22,48.14 31.62,48.14 31.82,48.34 31.82,55.14 32.02,55.34 34.02,55.34 35.02,56.34 35.02,58.34 34.82,58.54 34.22,58.54 v1(33.82,58.94)
JTG0_TMS/SWDIO: length 93.8
  TOP w0.14: v1(8.51,29.34) 7.37,28.19 4.95,28.19 3.56,29.59 3.56,46.1 2.29,47.37 2.29,55.24 2.92,55.88 v2(5.08,55.88)
  TOP w0.203: U1.C12 v1(34.62,59.74)
  L5_SIG w0.14: v2(5.08,55.88) P1.2
  BOTTOM w0.14: J3.48 8.51,29.34 v1(8.51,29.34) 18.29,29.34 18.8,29.84 18.8,38.99 20.32,40.51 20.32,44.45 20.7,44.83 26.03,44.83 26.22,45.02 26.22,56.74 26.42,56.94 32.42,56.94 32.62,57.14 32.62,59.14 32.82,59.34 U1.C12 v1(34.62,59.74)
N1: length 149.1
  TOP w0.14: v1(32.19,5.33) 31.69,5.84 24.38,5.84 22.35,7.87 v1(22.35,9.14)
  TOP w0.203: v1(30.62,59.74) U1.C8
  L4_SIG w0.14: v1(30.62,59.74) 30.22,59.34 22.22,59.34 v1(21.82,58.94) ; v1(22.35,9.14) 22.35,7.75 21.97,7.37 19.69,7.37 19.05,6.73 19.05,5.71 v1(18.67,5.33)
  L5_SIG w0.14: v1(21.82,58.94) 21.82,54.84 21.34,54.36 21.34,44.96 20.32,43.94 19.91,43.94 19.02,43.05 19.02,40.55 19.43,40.14 19.43,30.35 21.34,28.45 21.34,16 22.35,14.99 v1(22.35,9.14)
  BOTTOM w0.14: v1(32.19,5.33) 31.8,5.71 J2.52 31.8,8.38 32.05,8.64 38.23,8.64 38.61,9.02 52.7,9.02 53.98,10.29 53.98,16.51 52.7,17.78 52.7,21.08 51.69,22.1 51.69,32.89 53.85,35.05 53.85,40.26 54.99,41.4 J1.92 ; J2.30 24.81,8.51 24.26,9.06 24.26,9.4 24,9.65 22.86,9.65 v1(22.35,9.14) ; v1(18.67,5.33) 19.1,5.71 J2.12
N2: length 149.1
  TOP w0.203: v1(29.82,60.54) U1.B7
  L4_SIG w0.14: v1(29.82,60.54) 29.42,60.94 24.42,60.94 24.02,60.54 v1(23.02,60.54) ; v1(58.8,35.43) 59.82,34.42 59.82,24.77 60.32,24.26 61.98,24.26 62.36,23.88 62.36,11.18 61.72,10.54 56.26,10.54 55.5,9.78 53.59,9.78 53.09,9.27 53.09,4.83 52.2,3.94 46.99,3.94 v1(46.48,4.45) 46.86,4.83 46.86,5.46 45.34,6.99 38.61,6.99 36.96,8.64 33.66,8.64 32.64,7.62 30.86,7.62 28.57,9.91 24.26,9.91 v1(23.49,9.14)
  L5_SIG w0.14: v1(23.02,60.54) 22.22,59.74 22.22,54.61 21.72,54.11 21.72,44.96 20.62,43.86 20.62,42.94 19.42,41.74 19.42,40.74 19.82,40.34 19.82,30.73 21.84,28.7 21.84,16.38 22.86,15.37 22.86,9.78 v1(23.49,9.14)
  BOTTOM w0.14: v1(46.48,4.45) 46.4,4.06 J2.97 ; J2.28 24.18,8.46 v1(23.49,9.14) ; v1(58.8,35.43) 58.8,36.07 57.91,36.96 57.91,40.51 57.66,40.77 J1.90
N3: length 135.1
  TOP w0.14: v1(23.11,4.45) 23.56,4.89 30.86,4.89 v1(31.31,5.33)
  TOP w0.203: v1(29.82,59.74) U1.C7
  L4_SIG w0.14: v1(29.82,59.74) 29.42,60.14 21.82,60.14 v1(20.62,58.94) ; v1(30.99,8.13) 31.75,8.89 37.85,8.89 39.12,10.16 45.59,10.16 53.59,18.16 v1(53.59,18.67)
  L5_SIG w0.14: v1(20.62,58.94) 19.32,57.64 19.32,56.44 18.22,55.34 18.22,40.19 18.67,39.74 18.67,30.23 16.89,28.45 16.89,22.48 20.32,19.05 20.32,15.24 21.34,14.22 21.34,11.68 20.83,11.18 20.83,7.49 22.61,5.71 22.61,4.95 v1(23.11,4.45)
  BOTTOM w0.14: J2.23 22.91,4.06 v1(23.11,4.45) ; v1(31.31,5.33) 31.16,5.71 J2.50 31.16,7.75 v1(30.99,8.13) ; J1.88 54.99,40.13 54.36,39.5 54.36,34.29 52.58,32.51 52.58,24 54.36,22.23 54.36,19.43 v1(53.59,18.67)
N4: length 165.9
  TOP w0.14: v2(43.05,88.9) R115.2 ; v1(51.82,41.78) 49.26,44.34 v1(21.82,44.34)
  TOP w0.203: U1.C9 v1(31.42,59.74)
  L4_SIG w0.14: v1(18.41,58.93) 19.69,57.66 21.74,57.66 v1(23.02,58.94) 24.02,58.94 24.42,58.54 30.22,58.54 v1(31.42,59.74)
  L5_SIG w0.14: v1(25.78,8.13) 24.89,8.13 24.26,8.76 24.26,11.18 23.49,11.94 23.49,15.62 22.35,16.76 22.35,28.96 20.22,31.09 20.22,41.74 21.82,43.34 v1(21.82,44.34) 22.1,44.62 22.1,53.83 22.62,54.36 22.62,58.54 v1(23.02,58.94) ; v1(18.41,58.93) 18.41,65.91 20.57,68.07 20.57,72.26 21.84,73.53 21.84,86.49 22.61,87.25 28.45,87.25 29.84,88.65 40.26,88.65 41.15,89.54 42.42,89.54 v2(43.05,88.9)
  BOTTOM w0.14: J1.98 55.24,43.31 53.21,41.27 52.32,41.27 v1(51.82,41.78) ; v1(25.78,8.13) 26.86,8.13 27.35,7.64 J2.38 J2.37
N5: length 173.1
  TOP w0.14: v1(19.82,44.54) 20.22,44.94 20.22,45.54 20.62,45.94 23.22,45.94 24.42,44.74 49.75,44.74 v1(52.7,41.78) ; v2(50.16,88.9) R114.2
  TOP w0.203: v1(29.82,61.34) U1.A7
  L4_SIG w0.14: v1(29.82,61.34) 29.42,61.74 21.82,61.74 v1(20.62,60.54)
  L5_SIG w0.14: v2(50.16,88.9) 49.53,88.27 30.1,88.27 28.7,86.87 22.99,86.87 22.35,86.23 22.35,73.15 21.21,72.01 21.21,61.13 v1(20.62,60.54) 21.08,60.08 21.08,57.66 20.76,57.34 20.34,57.34 19.94,56.94 19.94,54.26 19.11,53.43 19.11,52.52 19.3,52.32 19.3,51.34 18.89,50.93 18.89,45.47 v1(19.82,44.54) 19.82,44.51 18.62,43.31 18.62,40.37 19.05,39.94 19.05,30.1 20.83,28.32 20.83,15.62 21.84,14.6 21.84,8.76 24,6.6 24.89,6.6 25.65,5.84 25.65,5.08 v1(26.29,4.45)
  BOTTOM w0.14: J1.100 55.37,43.94 53.21,41.78 v1(52.7,41.78) ; J2.35 26.72,4.06 v1(26.29,4.45) 26.72,4.87 J2.36
N6: length 60.9
  TOP w0.14: R70.1 v1(33.82,40.14)
  TOP w0.203: v1(29.82,46.14) U1.W7
  L4_SIG w0.14: v1(29.82,46.14) 30.22,45.74 30.22,42.34 32.42,40.14 v1(33.82,40.14) ; v1(26.16,5.33) 27.3,6.48 37.21,6.48 v1(38.35,5.33)
  L5_SIG w0.14: v1(38.35,5.33) 38.35,6.86 37.85,7.37 37.85,25.78 34.29,29.34 34.29,39.67 v1(33.82,40.14)
  BOTTOM w0.14: v1(26.16,5.33) 26.08,5.71 J2.34
N7: length 58.8
  TOP w0.203: v1(29.02,45.34) U1.Y6
  L4_SIG w0.14: v1(35.31,8.13) 34.54,7.37 30.73,7.37 28.45,9.65 24.64,9.65 v1(23.49,8.51)
  L5_SIG w0.14: v1(35.31,8.13) 35.31,10.79 35.94,11.43 35.94,12.45 34.29,14.1 34.29,17.02 35.05,17.78 35.05,18.8 34.42,19.43 34.42,20.57 35.05,21.21 35.05,25.02 31.62,28.45 31.62,32.35 30.48,33.5 30.48,37.93 29.42,38.99 29.42,43.94 29.02,44.34 v1(29.02,45.34)
  BOTTOM w0.14: J2.20 21.64,7.67 22.48,8.51 v1(23.49,8.51)
N8: length 72.3
  TOP w0.14: v1(38.35,4.45) 37.72,3.81 31.24,3.81 30.23,2.79 27.43,2.79 v1(26.29,1.65)
  TOP w0.203: v1(30.62,46.94) U1.V8
  L4_SIG w0.14: v1(26.29,1.65) 25.53,2.41 21.97,2.41 20.83,3.56 20.83,4.83 v1(20.32,5.33)
  L5_SIG w0.14: v1(30.62,46.94) U1.V8 32.42,47.34 33.27,46.49 33.27,37.1 33.93,36.45 33.93,28.81 36.83,25.91 36.83,18.44 36.7,18.31 36.7,13.72 37.21,13.21 37.21,7.11 37.85,6.48 37.85,4.95 v1(38.35,4.45)
  BOTTOM w0.14: v1(20.32,5.33) 20.37,5.71 J2.16 ; J2.33 26.08,2.16 v1(26.29,1.65)
N9: length 132.3
  TOP w0.14: v2(13.84,76.58) 13.46,76.44 U11.5 ; v1(18.16,8.13) 18.16,7.11 17.15,6.1 17.15,4.45 18.29,3.3 20.83,3.3 v1(22.48,1.65) 22.99,1.14 30.61,1.14 v1(31.12,1.65)
  TOP w0.203: v1(25.82,46.94) U1.V2
  L4_SIG w0.14: v1(9.02,43.69) 9.53,44.2 16.64,44.2 17.02,43.81 19.94,43.81 20.95,44.83 23.55,44.83 23.96,45.24 23.96,45.85 24.66,46.54 25.42,46.54 v1(25.82,46.94)
  L5_SIG w0.14: v1(18.16,8.13) 17.27,7.24 11.68,7.24 7.37,11.56 7.37,25.27 7.11,25.53 7.11,41.02 9.02,42.93 v1(9.02,43.69) 6.99,45.72 6.99,47.37 7.62,48.01 7.62,55.5 5.84,57.28 5.84,72.64 6.6,73.41 12.45,73.41 12.95,73.91 12.95,75.69 v2(13.84,76.58)
  BOTTOM w0.14: J2.49 31.16,2.16 v1(31.12,1.65) ; J2.10 18.46,7.62 v1(18.16,8.13) ; J2.21 22.27,2.16 v1(22.48,1.65)
N10: length 132.6
  TOP w0.14: v2(11.05,78.74) 11.43,78.39 U11.2 ; v1(17.65,5.33) 17.65,4.7 18.41,3.94 20.83,3.94 v1(21.34,4.45) 22.23,3.56 29.34,3.56 v1(30.23,4.45)
  TOP w0.203: v1(26.62,47.74) U1.U3
  L4_SIG w0.14: v2(5.21,46.48) 6.6,46.48 7.24,47.12 8.51,47.12 9.91,45.72 14.99,45.72 15.37,46.1 23.11,46.1 24.35,47.34 26.22,47.34 v1(26.62,47.74)
  L5_SIG w0.14: v1(17.65,5.33) 16.13,6.86 11.43,6.86 6.99,11.3 6.99,24.89 6.6,25.27 6.6,41.02 4.32,43.31 4.32,45.59 v2(5.21,46.48) 7.11,48.39 7.11,55.24 5.33,57.02 5.33,77.6 6.48,78.74 v2(11.05,78.74)
  BOTTOM w0.14: v1(17.65,5.33) 17.83,5.71 J2.8 ; J2.19 21.64,4.06 v1(21.34,4.45) ; v1(30.23,4.45) 30.53,4.06 J2.47
N11: length 131.8
  TOP w0.14: v2(14.73,76.58) 15.89,77.74 U11.12 ; v1(17.4,8.13) 17.4,7.43 16.89,6.92 16.89,4 18.03,2.86 19.69,2.86 v1(20.95,1.65)
  TOP w0.203: v1(25.02,46.94) U1.V1
  L4_SIG w0.14: v1(20.95,1.65) 21.46,1.14 29.08,1.14 v1(29.59,1.65) ; v2(8.13,46.48) 9.27,45.34 15.49,45.34 16,45.85 23.37,45.85 24.46,46.94 v1(25.02,46.94)
  L5_SIG w0.14: v2(14.73,76.58) 13.59,75.44 13.59,73.53 12.95,72.9 8.38,72.9 7.49,72.01 7.49,71.12 6.86,70.48 6.86,64.26 6.35,63.75 6.35,57.53 8.13,55.75 8.13,51.56 8.89,50.8 8.89,47.24 v2(8.13,46.48) 9.65,44.96 9.65,42.8 7.62,40.77 7.62,26.16 7.87,25.91 7.87,11.68 11.94,7.62 16.89,7.62 v1(17.4,8.13)
  BOTTOM w0.14: v1(29.59,1.65) 29.89,2.16 J2.45 ; J2.17 21,2.16 v1(20.95,1.65) ; J2.6 17.19,7.62 v1(17.4,8.13) ; R90.2 v2(14.73,76.58)
N12: length 122.5
  TOP w0.14: v1(29.21,4.45) 28.7,3.94 22.59,3.94 21.64,4.89 20.78,4.89 v1(20.32,4.45) ; v2(20.19,76.07) 19.91,75.79 U11.9
  TOP w0.203: v1(27.42,48.54) U1.T3
  L4_SIG w0.14: v1(12.7,41.53) 27.81,41.53 28.19,41.91 28.19,44.27 27.83,44.64 27.83,48.13 v1(27.42,48.54)
  L5_SIG w0.14: v1(16.51,8.13) 15.75,8.89 14.48,8.89 13.46,9.91 13.46,28.19 12.19,29.46 12.19,32.77 12.7,33.27 12.7,34.92 11.43,36.2 11.43,40.26 v1(12.7,41.53) 14.22,43.05 14.22,65.79 15.11,66.68 15.11,69.47 16.76,71.12 16.76,75.06 17.78,76.07 v2(20.19,76.07)
  BOTTOM w0.14: R91.2 18.54,76.07 v2(20.19,76.07) ; J2.43 29.26,4.06 v1(29.21,4.45) ; J2.15 20.37,4.06 v1(20.32,4.45) 19.88,4.89 17.13,4.89 16.56,5.46 J2.4 16.56,7.75 v1(16.51,8.13)
